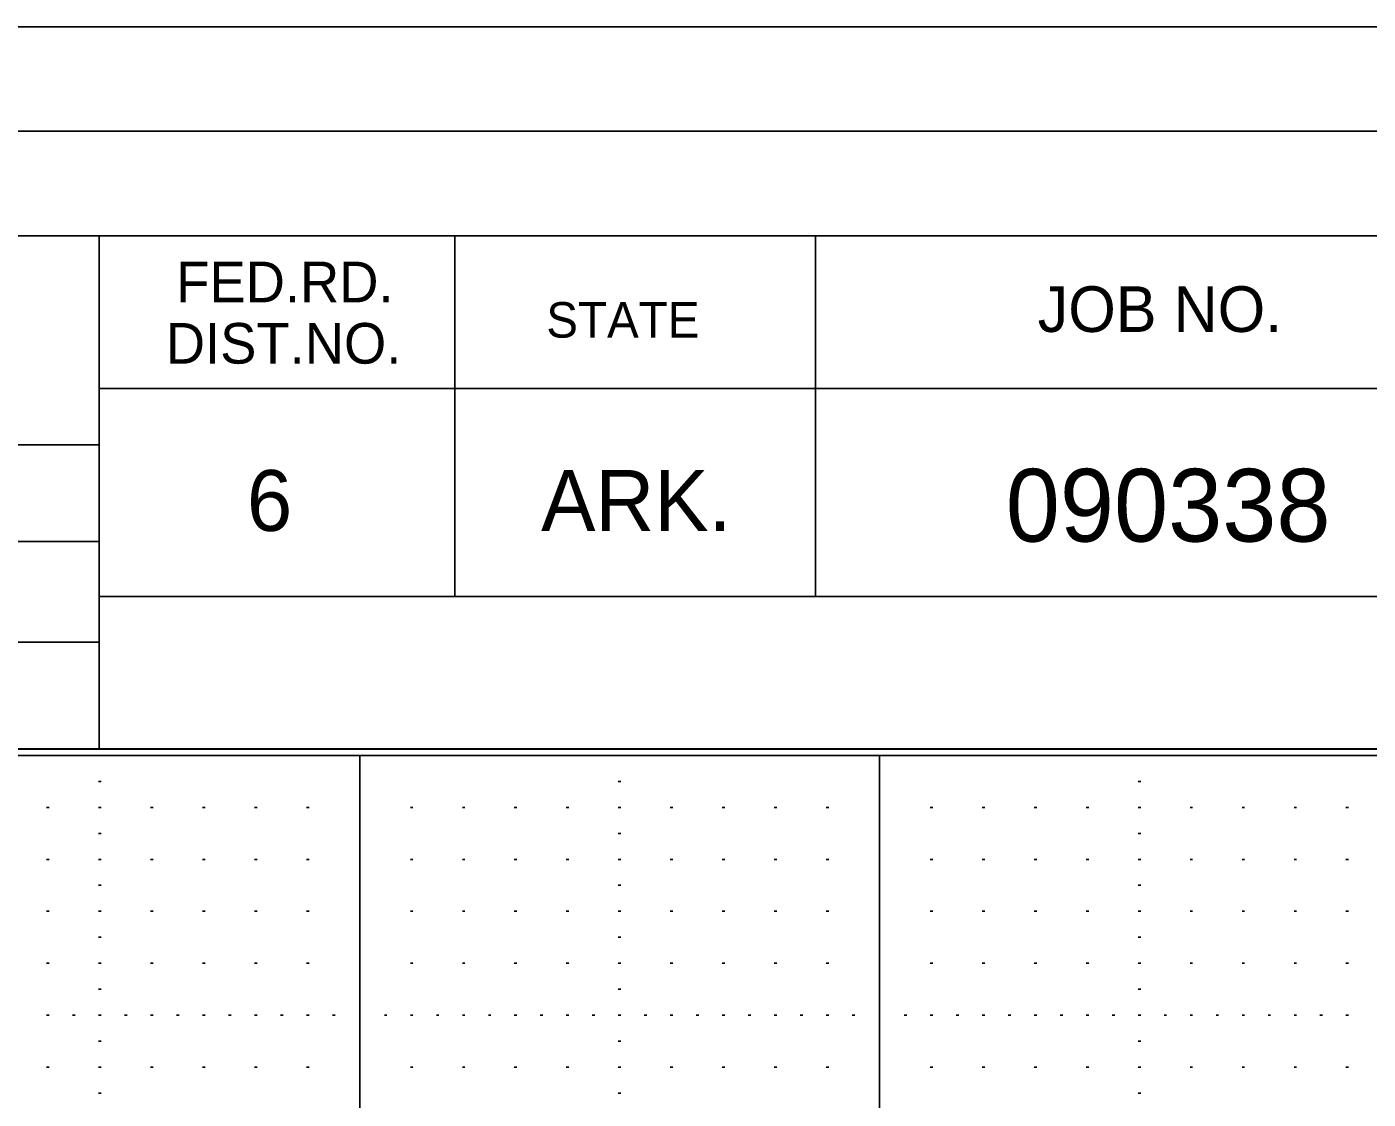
# Model space of a CAD drawing. Extents: x -3.6 to 32.1, y -0.4 to 25.6.
# Drawn here: x 27.168 to 29.748, y 18.884 to 20.947 of the extents above; entities that cross this region are included whole.
import ezdxf

# ---------------------------------------------------------------- set-up
doc = ezdxf.new("R2010")
doc.units = 0
for name, color, linetype in [('Level 1', 7, 'Continuous'), ('Level 4', 7, 'Continuous'), ('Level 5', 7, 'Continuous'), ('Level 62', 7, 'Continuous'), ('Level 63', 7, 'Continuous'), ('Level 63 Full', 7, 'Continuous'), ('R_Border', 7, 'Continuous'), ('R_Border Prem', 7, 'Continuous')]:
    doc.layers.add(name, color=color, linetype=linetype)

msp = doc.modelspace()

# ---------------------------------------------------------------- linework, layer by layer
at = {"layer": 'Level 1'}
for p, q in [((27.307, 20.5449), (27.307, 19.5569)), ((27.991, 20.5449), (27.991, 19.8509)), ((28.685, 20.5449), (28.685, 19.8509)), ((31.617, 20.2509), (27.307, 20.2509)), ((25.353, 20.1429), (27.307, 20.1429)), ((25.353, 19.9569), (27.307, 19.9569)), ((31.617, 19.8509), (27.307, 19.8509)), ((27.603, 19.8509), (31.617, 19.8509)), ((25.353, 19.7629), (27.307, 19.7629)), ((31.617, 19.5569), (25.353, 19.5569))]:
    msp.add_line(p, q, dxfattribs=at)
at = {"layer": 'Level 4'}
for p, q in [((31.617, 19.545), (-0.001, 19.545)), ((27.808, 0.545), (27.808, 19.545)), ((28.808, 0.545), (28.808, 19.545))]:
    msp.add_line(p, q, dxfattribs=at)
at = {"layer": 'Level 5'}
for p, q in [((27.3055, 19.495), (27.3105, 19.495)), ((28.3055, 19.495), (28.3105, 19.495)), ((29.3055, 19.495), (29.3105, 19.495)), ((27.2055, 19.445), (27.2105, 19.445)), ((27.3055, 19.445), (27.3105, 19.445)), ((27.4055, 19.445), (27.4105, 19.445)), ((27.5055, 19.445), (27.5105, 19.445)), ((27.6055, 19.445), (27.6105, 19.445)), ((27.7055, 19.445), (27.7105, 19.445)), ((27.9055, 19.445), (27.9105, 19.445)), ((28.0055, 19.445), (28.0105, 19.445)), ((28.1055, 19.445), (28.1105, 19.445)), ((28.2055, 19.445), (28.2105, 19.445)), ((28.3055, 19.445), (28.3105, 19.445)), ((28.4055, 19.445), (28.4105, 19.445)), ((28.5055, 19.445), (28.5105, 19.445)), ((28.6055, 19.445), (28.6105, 19.445)), ((28.7055, 19.445), (28.7105, 19.445)), ((28.9055, 19.445), (28.9105, 19.445)), ((29.0055, 19.445), (29.0105, 19.445)), ((29.1055, 19.445), (29.1105, 19.445)), ((29.2055, 19.445), (29.2105, 19.445)), ((29.3055, 19.445), (29.3105, 19.445)), ((29.4055, 19.445), (29.4105, 19.445)), ((29.5055, 19.445), (29.5105, 19.445)), ((29.6055, 19.445), (29.6105, 19.445)), ((29.7055, 19.445), (29.7105, 19.445)), ((27.3055, 19.395), (27.3105, 19.395)), ((28.3055, 19.395), (28.3105, 19.395)), ((29.3055, 19.395), (29.3105, 19.395)), ((27.2055, 19.345), (27.2105, 19.345)), ((27.3055, 19.345), (27.3105, 19.345)), ((27.4055, 19.345), (27.4105, 19.345)), ((27.5055, 19.345), (27.5105, 19.345)), ((27.6055, 19.345), (27.6105, 19.345)), ((27.7055, 19.345), (27.7105, 19.345)), ((27.9055, 19.345), (27.9105, 19.345)), ((28.0055, 19.345), (28.0105, 19.345)), ((28.1055, 19.345), (28.1105, 19.345)), ((28.2055, 19.345), (28.2105, 19.345)), ((28.3055, 19.345), (28.3105, 19.345)), ((28.4055, 19.345), (28.4105, 19.345)), ((28.5055, 19.345), (28.5105, 19.345)), ((28.6055, 19.345), (28.6105, 19.345)), ((28.7055, 19.345), (28.7105, 19.345)), ((28.9055, 19.345), (28.9105, 19.345)), ((29.0055, 19.345), (29.0105, 19.345)), ((29.1055, 19.345), (29.1105, 19.345)), ((29.2055, 19.345), (29.2105, 19.345)), ((29.3055, 19.345), (29.3105, 19.345)), ((29.4055, 19.345), (29.4105, 19.345)), ((29.5055, 19.345), (29.5105, 19.345)), ((29.6055, 19.345), (29.6105, 19.345)), ((29.7055, 19.345), (29.7105, 19.345)), ((27.3055, 19.295), (27.3105, 19.295)), ((28.3055, 19.295), (28.3105, 19.295)), ((29.3055, 19.295), (29.3105, 19.295)), ((27.2055, 19.245), (27.2105, 19.245)), ((27.3055, 19.245), (27.3105, 19.245)), ((27.4055, 19.245), (27.4105, 19.245)), ((27.5055, 19.245), (27.5105, 19.245)), ((27.6055, 19.245), (27.6105, 19.245)), ((27.7055, 19.245), (27.7105, 19.245)), ((27.9055, 19.245), (27.9105, 19.245)), ((28.0055, 19.245), (28.0105, 19.245)), ((28.1055, 19.245), (28.1105, 19.245)), ((28.2055, 19.245), (28.2105, 19.245)), ((28.3055, 19.245), (28.3105, 19.245)), ((28.4055, 19.245), (28.4105, 19.245)), ((28.5055, 19.245), (28.5105, 19.245)), ((28.6055, 19.245), (28.6105, 19.245)), ((28.7055, 19.245), (28.7105, 19.245)), ((28.9055, 19.245), (28.9105, 19.245)), ((29.0055, 19.245), (29.0105, 19.245)), ((29.1055, 19.245), (29.1105, 19.245)), ((29.2055, 19.245), (29.2105, 19.245)), ((29.3055, 19.245), (29.3105, 19.245)), ((29.4055, 19.245), (29.4105, 19.245)), ((29.5055, 19.245), (29.5105, 19.245)), ((29.6055, 19.245), (29.6105, 19.245)), ((29.7055, 19.245), (29.7105, 19.245)), ((27.3055, 19.195), (27.3105, 19.195)), ((28.3055, 19.195), (28.3105, 19.195)), ((29.3055, 19.195), (29.3105, 19.195)), ((27.2055, 19.145), (27.2105, 19.145)), ((27.3055, 19.145), (27.3105, 19.145)), ((27.4055, 19.145), (27.4105, 19.145)), ((27.5055, 19.145), (27.5105, 19.145)), ((27.6055, 19.145), (27.6105, 19.145)), ((27.7055, 19.145), (27.7105, 19.145)), ((27.9055, 19.145), (27.9105, 19.145)), ((28.0055, 19.145), (28.0105, 19.145)), ((28.1055, 19.145), (28.1105, 19.145)), ((28.2055, 19.145), (28.2105, 19.145)), ((28.3055, 19.145), (28.3105, 19.145)), ((28.4055, 19.145), (28.4105, 19.145)), ((28.5055, 19.145), (28.5105, 19.145)), ((28.6055, 19.145), (28.6105, 19.145)), ((28.7055, 19.145), (28.7105, 19.145)), ((28.9055, 19.145), (28.9105, 19.145)), ((29.0055, 19.145), (29.0105, 19.145)), ((29.1055, 19.145), (29.1105, 19.145)), ((29.2055, 19.145), (29.2105, 19.145)), ((29.3055, 19.145), (29.3105, 19.145)), ((29.4055, 19.145), (29.4105, 19.145)), ((29.5055, 19.145), (29.5105, 19.145)), ((29.6055, 19.145), (29.6105, 19.145)), ((29.7055, 19.145), (29.7105, 19.145)), ((27.3055, 19.095), (27.3105, 19.095)), ((28.3055, 19.095), (28.3105, 19.095)), ((29.3055, 19.095), (29.3105, 19.095)), ((27.2055, 19.045), (27.2105, 19.045)), ((27.2555, 19.045), (27.2605, 19.045)), ((27.3055, 19.045), (27.3105, 19.045)), ((27.3555, 19.045), (27.3605, 19.045)), ((27.4055, 19.045), (27.4105, 19.045)), ((27.4555, 19.045), (27.4605, 19.045)), ((27.5055, 19.045), (27.5105, 19.045)), ((27.5555, 19.045), (27.5605, 19.045)), ((27.6055, 19.045), (27.6105, 19.045)), ((27.6555, 19.045), (27.6605, 19.045)), ((27.7055, 19.045), (27.7105, 19.045)), ((27.7555, 19.045), (27.7605, 19.045)), ((27.8555, 19.045), (27.8605, 19.045)), ((27.9055, 19.045), (27.9105, 19.045)), ((27.9555, 19.045), (27.9605, 19.045)), ((28.0055, 19.045), (28.0105, 19.045)), ((28.0555, 19.045), (28.0605, 19.045)), ((28.1055, 19.045), (28.1105, 19.045)), ((28.1555, 19.045), (28.1605, 19.045)), ((28.2055, 19.045), (28.2105, 19.045)), ((28.2555, 19.045), (28.2605, 19.045)), ((28.3055, 19.045), (28.3105, 19.045)), ((28.3555, 19.045), (28.3605, 19.045)), ((28.4055, 19.045), (28.4105, 19.045)), ((28.4555, 19.045), (28.4605, 19.045)), ((28.5055, 19.045), (28.5105, 19.045)), ((28.5555, 19.045), (28.5605, 19.045)), ((28.6055, 19.045), (28.6105, 19.045)), ((28.6555, 19.045), (28.6605, 19.045)), ((28.7055, 19.045), (28.7105, 19.045)), ((28.7555, 19.045), (28.7605, 19.045)), ((28.8555, 19.045), (28.8605, 19.045)), ((28.9055, 19.045), (28.9105, 19.045)), ((28.9555, 19.045), (28.9605, 19.045)), ((29.0055, 19.045), (29.0105, 19.045)), ((29.0555, 19.045), (29.0605, 19.045)), ((29.1055, 19.045), (29.1105, 19.045)), ((29.1555, 19.045), (29.1605, 19.045)), ((29.2055, 19.045), (29.2105, 19.045)), ((29.2555, 19.045), (29.2605, 19.045)), ((29.3055, 19.045), (29.3105, 19.045)), ((29.3555, 19.045), (29.3605, 19.045)), ((29.4055, 19.045), (29.4105, 19.045)), ((29.4555, 19.045), (29.4605, 19.045)), ((29.5055, 19.045), (29.5105, 19.045)), ((29.5555, 19.045), (29.5605, 19.045)), ((29.6055, 19.045), (29.6105, 19.045)), ((29.6555, 19.045), (29.6605, 19.045)), ((29.7055, 19.045), (29.7105, 19.045)), ((27.3055, 18.995), (27.3105, 18.995)), ((28.3055, 18.995), (28.3105, 18.995)), ((29.3055, 18.995), (29.3105, 18.995)), ((27.2055, 18.945), (27.2105, 18.945)), ((27.3055, 18.945), (27.3105, 18.945)), ((27.4055, 18.945), (27.4105, 18.945)), ((27.5055, 18.945), (27.5105, 18.945)), ((27.6055, 18.945), (27.6105, 18.945)), ((27.7055, 18.945), (27.7105, 18.945)), ((27.9055, 18.945), (27.9105, 18.945)), ((28.0055, 18.945), (28.0105, 18.945)), ((28.1055, 18.945), (28.1105, 18.945)), ((28.2055, 18.945), (28.2105, 18.945)), ((28.3055, 18.945), (28.3105, 18.945)), ((28.4055, 18.945), (28.4105, 18.945)), ((28.5055, 18.945), (28.5105, 18.945)), ((28.6055, 18.945), (28.6105, 18.945)), ((28.7055, 18.945), (28.7105, 18.945)), ((28.9055, 18.945), (28.9105, 18.945)), ((29.0055, 18.945), (29.0105, 18.945)), ((29.1055, 18.945), (29.1105, 18.945)), ((29.2055, 18.945), (29.2105, 18.945)), ((29.3055, 18.945), (29.3105, 18.945)), ((29.4055, 18.945), (29.4105, 18.945)), ((29.5055, 18.945), (29.5105, 18.945)), ((29.6055, 18.945), (29.6105, 18.945)), ((29.7055, 18.945), (29.7105, 18.945)), ((27.3055, 18.895), (27.3105, 18.895)), ((28.3055, 18.895), (28.3105, 18.895)), ((29.3055, 18.895), (29.3105, 18.895))]:
    msp.add_line(p, q, dxfattribs=at)
at = {"layer": 'Level 62'}
msp.add_line((30.8075, 19.5579), (26.9998, 19.558), dxfattribs=at)
at = {"layer": 'Level 63'}
msp.add_lwpolyline([(-1.263, -0.2005), (32.067, -0.2005), (32.067, 20.7465), (-1.263, 20.7465)], close=True, dxfattribs=at)
at = {"layer": 'Level 63 Full'}
msp.add_lwpolyline([(32.017, -0.403), (-3.583, -0.403), (-3.583, 20.947), (32.017, 20.947)], close=True, dxfattribs=at)
at = {"layer": 'R_Border Prem'}
msp.add_line((-0.001, 20.545), (31.617, 20.545), dxfattribs=at)

# ---------------------------------------------------------------- texts
at = {"layer": 'Level 1'}
for s, height, p in [('FED.RD.', 0.07819, (27.455, 20.4169)), ('JOB NO.', 0.08792, (29.1124, 20.3598)), ('STATE', 0.0684, (28.167, 20.3489)), ('DIST.NO.', 0.07819, (27.435, 20.2989)), ('6', 0.1172, (27.591, 19.9769)), ('ARK.', 0.11723, (28.157, 19.9769)), ('090338', 0.14, (29.051, 19.9564))]:
    msp.add_text(s, height=height, dxfattribs=at).set_placement(p)
at = {"layer": 'R_Border'}
msp.add_text('JOB NO.', height=0.08792, dxfattribs=at).set_placement((29.1124, 20.3598))

doc.saveas('drawing.dxf')
